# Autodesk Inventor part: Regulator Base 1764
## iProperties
Created: 2010-02
Part Number: Regulator Base 1764
Document SubType Name: Modeling
Designer: jgehrig
Density: 1 g/cm^3
Author: jgehrig
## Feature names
1. Extrusion1
2. Chamfer1
3. Extrusion2
4. Extrusion3
5. Extrusion4
